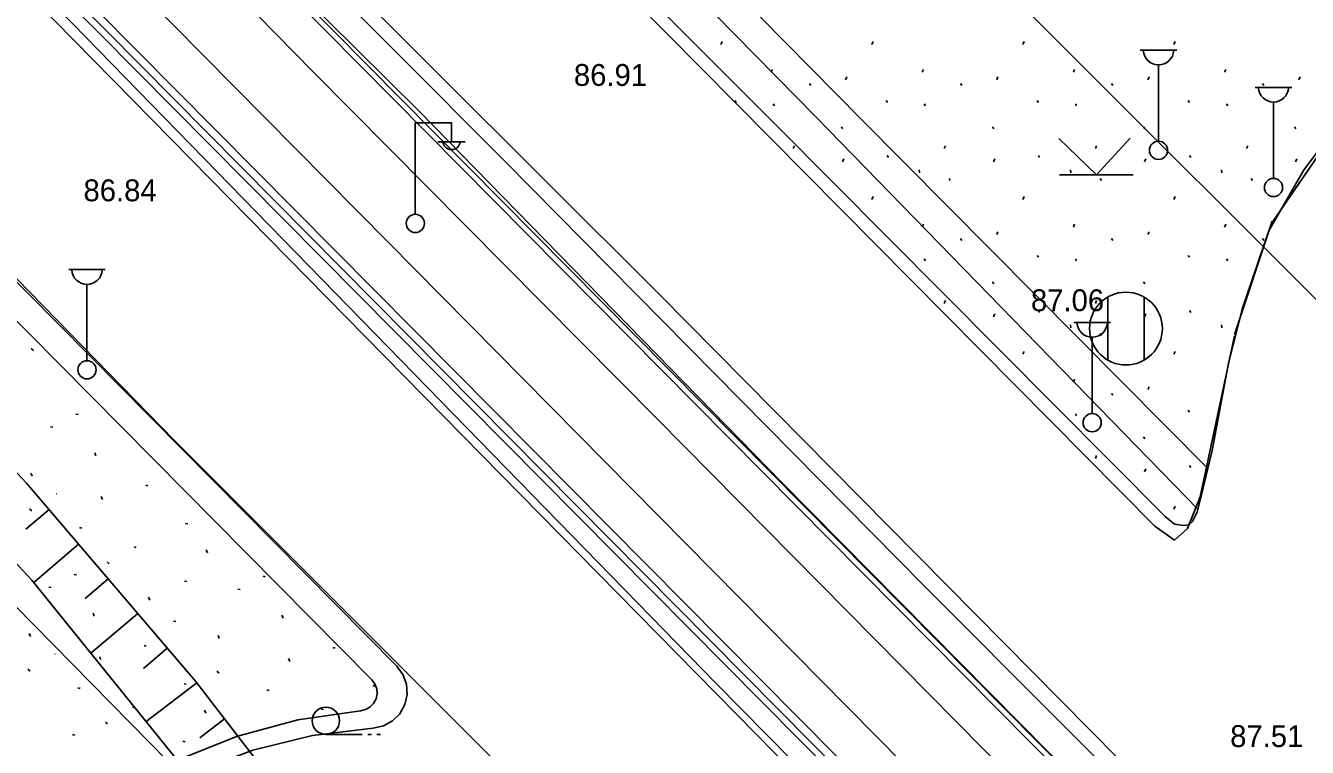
# Model space of a CAD drawing. Extents: x 412225 to 413380, y 4456471 to 4457189.
# Drawn here: x 412532.8 to 412603.2, y 4456807.4 to 4456847.1 of the extents above; entities that cross this region are included whole.
import ezdxf

# ---------------------------------------------------------------- set-up
doc = ezdxf.new("R2010")
doc.units = 0
for name, color, linetype in [('0_HALİHAZIR', 7, 'Continuous'), ('0_KADASTRO', 7, 'Continuous'), ('KALDIRIM', 7, 'Continuous'), ('Level 41', 7, 'Continuous'), ('Level 62', 7, 'Continuous'), ('Level 8', 7, 'Continuous')]:
    doc.layers.add(name, color=color, linetype=linetype)

msp = doc.modelspace()

# ---------------------------------------------------------------- linework, layer by layer
at = {"layer": '0_HALİHAZIR'}
for p, q in [((412594.026, 4456845.719), (412596.026, 4456845.719)), ((412595.026, 4456840.719), (412595.026, 4456844.912)), ((412600.335, 4456843.674), (412602.335, 4456843.674)), ((412601.335, 4456838.674), (412601.335, 4456842.867)), ((412554.212, 4456836.725), (412554.212, 4456841.726)), ((412554.212, 4456841.726), (412556.212, 4456841.726)), ((412556.212, 4456840.726), (412556.212, 4456841.726)), ((412591.613, 4456838.879), (412589.553, 4456840.869)), ((412591.613, 4456838.879), (412593.464, 4456840.889)), ((412555.452, 4456840.686), (412556.952, 4456840.686)), ((412589.593, 4456838.879), (412593.633, 4456838.879)), ((412535.199, 4456833.662), (412537.199, 4456833.662)), ((412536.199, 4456828.662), (412536.199, 4456832.855)), ((412592.236, 4456828.696), (412592.236, 4456832.156)), ((412594.236, 4456828.696), (412594.236, 4456832.156)), ((412590.383, 4456830.757), (412592.383, 4456830.757)), ((412591.383, 4456825.757), (412591.383, 4456829.95)), ((412534.114, 4456820.48), (412532.847, 4456819.399)), ((412535.737, 4456818.578), (412533.274, 4456816.477)), ((412537.36, 4456816.677), (412536.103, 4456815.604)), ((412538.982, 4456814.775), (412536.419, 4456812.587)), ((412540.605, 4456812.873), (412539.298, 4456811.758)), ((412542.224, 4456810.968), (412539.453, 4456808.834)), ((412543.75, 4456808.988), (412542.388, 4456807.938)), ((412549.31, 4456808.134), (412551.31, 4456808.134)), ((412551.61, 4456808.134), (412551.81, 4456808.134)), ((412552.11, 4456808.134), (412552.31, 4456808.134))]:
    msp.add_line(p, q, dxfattribs=at)
for points in [[(412644.931, 4456753.555), (412630.555, 4456767.782), (412604.684, 4456793.709), (412582.154, 4456816.287), (412559.135, 4456839.628), (412534.75, 4456864.124), (412499.888, 4456899.345), (412487.433, 4456911.736), (412459.99, 4456939.333), (412440.337, 4456959.115), (412419.902, 4456979.921), (412392.691, 4457007.039), (412362.588, 4457037.58), (412334.209, 4457066.321), (412297.701, 4457103.437), (412284.18, 4457117.149)], [(412284.17, 4457116.265), (412296.803, 4457102.771), (412316.426, 4457082.291), (412338.061, 4457060.18), (412363.233, 4457034.899), (412383.867, 4457014.022), (412425.083, 4456972.499), (412446.131, 4456951.075), (412463.226, 4456933.647), (412501.75, 4456894.857), (412523.558, 4456872.918), (412554.446, 4456842.344)], [(412283.985, 4457100.322), (412303.353, 4457080.961), (412332.911, 4457051.149), (412362.488, 4457021.336), (412400.253, 4456983.455), (412425.306, 4456957.949), (412451.956, 4456931.175), (412483.613, 4456899.459), (412507.045, 4456875.463), (412533.953, 4456848.693), (412570.746, 4456810.938), (412594.382, 4456786.967), (412618.72, 4456762.275), (412633.267, 4456747.178), (412636.335, 4456744.215)], [(412645.421, 4456754.062), (412629.127, 4456770.178), (412599.147, 4456800.409), (412567.615, 4456832.31), (412536.489, 4456863.396), (412502.72, 4456897.599), (412471.675, 4456928.735), (412445.148, 4456955.565), (412406.259, 4456994.837)], [(412637.165, 4456746.318), (412618.159, 4456765.78), (412589.798, 4456794.375), (412560.702, 4456823.748), (412525.834, 4456858.92), (412495.532, 4456889.87), (412469.975, 4456915.531), (412420.275, 4456965.756), (412393.731, 4456992.619)], [(412414.019, 4456980.608), (412430.818, 4456963.728), (412462.102, 4456931.987), (412481.52, 4456912.466), (412499.923, 4456893.817), (412530.253, 4456863.229), (412548.59, 4456844.546), (412567.492, 4456825.478), (412597.357, 4456795.212), (412619.629, 4456772.724)], [(412412.412, 4456976.824), (412430.58, 4456958.484), (412471.136, 4456917.576), (412494.611, 4456893.791), (412529.094, 4456859.09), (412552.718, 4456835.192), (412591.392, 4456796.015), (412615.481, 4456771.779), (412632.916, 4456754.119)], [(412635.095, 4456744.706), (412621.293, 4456758.968), (412594.514, 4456786.189), (412564.28, 4456816.959), (412527.989, 4456853.886), (412497.963, 4456883.985), (412468.818, 4456913.357), (412423.738, 4456958.933), (412408.728, 4456974.086)], [(412597.174, 4456820.503), (412576.231, 4456842.04), (412561.741, 4456856.791)], [(412565.002, 4456855.835), (412578.684, 4456841.949), (412597.738, 4456822.746)], [(412611.653, 4456848.275), (412608.162, 4456845.364), (412605.073, 4456841.916), (412602.977, 4456839.108), (412601.086, 4456835.793), (412599.636, 4456831.548), (412598.859, 4456828.528), (412597.976, 4456823.732), (412597.387, 4456821.291), (412597.138, 4456820.367), (412596.899, 4456819.837), (412596.688, 4456819.654), (412596.393, 4456819.6), (412595.898, 4456819.675), (412595.383, 4456820.111), (412574.046, 4456841.577), (412560.867, 4456854.796)], [(412554.446, 4456842.344), (412574.337, 4456821.975), (412608.572, 4456787.352), (412635.895, 4456760.057), (412643.635, 4456752.216)], [(412528.743, 4456836.847), (412540.992, 4456824.288), (412559.224, 4456806.047), (412568.503, 4456796.519), (412569.191, 4456795.526), (412569.313, 4456795.068), (412569.042, 4456794.505), (412568.57, 4456794.169), (412567.618, 4456794.057), (412564.023, 4456793.79), (412559.479, 4456793.181), (412554.595, 4456792.173), (412549.493, 4456790.405), (412546.13, 4456788.844), (412542.472, 4456786.095), (412539.525, 4456783.093), (412537.043, 4456779.687), (412534.635, 4456775.789), (412533.752, 4456774.346), (412533.28, 4456774.06), (412532.886, 4456773.972), (412532.31, 4456774.062)], [(412524.256, 4456831.161), (412532.872, 4456821.935), (412542.154, 4456811.059), (412548.102, 4456803.338), (412550.217, 4456799.244), (412550.951, 4456797.332), (412551.196, 4456796.316), (412551.092, 4456795.608), (412550.66, 4456794.812), (412550.141, 4456794.328), (412549.147, 4456793.722), (412547.453, 4456792.678), (412544.824, 4456790.371), (412541.569, 4456787.003), (412538.882, 4456784.219), (412536.669, 4456781.54), (412535.299, 4456779.679), (412534.332, 4456778.383), (412533.704, 4456777.536), (412533.311, 4456777.415), (412532.242, 4456777.481)], [(412532.295, 4456782.824), (412533.199, 4456782.805), (412534.47, 4456783.53), (412535.823, 4456785.423), (412538.722, 4456788.408), (412542.514, 4456792.063), (412545.144, 4456794.354), (412546.599, 4456796.002), (412547.018, 4456797.685), (412546.2, 4456799.629), (412544.925, 4456801.385), (412541.266, 4456806.591), (412533.164, 4456816.614), (412521.975, 4456828.646)]]:
    msp.add_lwpolyline(points, dxfattribs=at)
for centre, radius in [((412595.026, 4456840.219), 0.5), ((412601.335, 4456838.174), 0.5), ((412554.222, 4456836.201), 0.5), ((412593.236, 4456830.426), 2), ((412536.199, 4456828.162), 0.5), ((412591.383, 4456825.257), 0.5), ((412549.31, 4456808.884), 0.75)]:
    msp.add_circle(centre, radius, dxfattribs=at)
for centre, radius, start, end in [((412595.026, 4456845.749), 0.837, 183.298, 356.90719), ((412601.335, 4456843.704), 0.837, 183.298, 356.90719), ((412556.212, 4456840.729), 0.474, 184.83843, 355.14641), ((412536.199, 4456833.692), 0.837, 183.298, 356.90719), ((412591.383, 4456830.787), 0.837, 183.298, 356.90719)]:
    msp.add_arc(centre, radius, start, end, dxfattribs=at)
at = {"layer": '0_KADASTRO'}
msp.add_lwpolyline([(412511.64, 4456802.61), (412523.869, 4456823.705), (412617.056, 4456728.859), (412543.593, 4456703.12), (412527.466, 4456778.138), (412524.42, 4456784.89), (412522.24, 4456788.56), (412519.52, 4456792.85), (412512.99, 4456801.24)], close=True, dxfattribs=at)
at = {"layer": 'KALDIRIM'}
msp.add_line((412528.505, 4456834.72), (412551.839, 4456811.132), dxfattribs=at)
for points in [[(412551.215, 4456809.433), (412551.489, 4456809.497), (412551.735, 4456809.635), (412551.933, 4456809.836), (412552.067, 4456810.084), (412552.126, 4456810.36), (412552.106, 4456810.641), (412552.007, 4456810.906), (412551.839, 4456811.132)], [(412551.215, 4456809.433), (412547.768, 4456808.928), (412544.404, 4456808.02), (412541.171, 4456806.722), (412538.114, 4456805.052), (412535.275, 4456803.034), (412532.693, 4456800.694), (412530.406, 4456798.067), (412528.444, 4456795.188), (412526.835, 4456792.098), (412525.601, 4456788.84), (412524.761, 4456785.459)]]:
    msp.add_lwpolyline(points, dxfattribs=at)
at = {"layer": 'Level 41'}
for p, q in [((412570.993, 4456846.032), (412571.065, 4456846.192)), ((412579.286, 4456846.032), (412579.358, 4456846.192)), ((412587.579, 4456846.032), (412587.651, 4456846.192)), ((412595.872, 4456846.032), (412595.944, 4456846.192)), ((412573.765, 4456844.502), (412573.835, 4456844.662)), ((412577.848, 4456844.094), (412577.919, 4456844.254)), ((412582.058, 4456844.502), (412582.128, 4456844.662)), ((412586.141, 4456844.094), (412586.212, 4456844.254)), ((412590.351, 4456844.502), (412590.421, 4456844.662)), ((412594.434, 4456844.094), (412594.505, 4456844.254)), ((412598.644, 4456844.502), (412598.714, 4456844.662)), ((412602.727, 4456844.094), (412602.798, 4456844.254)), ((412575.86, 4456843.886), (412575.931, 4456843.78)), ((412584.153, 4456843.886), (412584.224, 4456843.78)), ((412592.446, 4456843.886), (412592.517, 4456843.78)), ((412600.739, 4456843.886), (412600.81, 4456843.78)), ((412571.775, 4456842.957), (412571.846, 4456842.85)), ((412580.068, 4456842.957), (412580.139, 4456842.85)), ((412588.361, 4456842.957), (412588.432, 4456842.85)), ((412596.654, 4456842.957), (412596.725, 4456842.85)), ((412573.874, 4456842.765), (412573.945, 4456842.658)), ((412582.167, 4456842.765), (412582.238, 4456842.658)), ((412590.46, 4456842.765), (412590.531, 4456842.658)), ((412598.753, 4456842.765), (412598.824, 4456842.658)), ((412577.612, 4456841.504), (412577.683, 4456841.397)), ((412585.905, 4456841.504), (412585.976, 4456841.397)), ((412594.198, 4456841.504), (412594.269, 4456841.397)), ((412602.491, 4456841.504), (412602.562, 4456841.397)), ((412574.971, 4456840.311), (412575.042, 4456840.47)), ((412583.264, 4456840.311), (412583.335, 4456840.47)), ((412591.557, 4456840.311), (412591.628, 4456840.47)), ((412599.85, 4456840.311), (412599.921, 4456840.47)), ((412577.67, 4456839.582), (412577.742, 4456839.742)), ((412580.135, 4456839.927), (412580.206, 4456839.82)), ((412585.963, 4456839.582), (412586.035, 4456839.742)), ((412588.428, 4456839.927), (412588.499, 4456839.82)), ((412594.256, 4456839.582), (412594.328, 4456839.742)), ((412596.721, 4456839.927), (412596.792, 4456839.82)), ((412602.549, 4456839.582), (412602.621, 4456839.742)), ((412581.893, 4456839.136), (412581.911, 4456838.976)), ((412583.523, 4456838.666), (412583.593, 4456838.559)), ((412590.186, 4456839.136), (412590.204, 4456838.976)), ((412591.816, 4456838.666), (412591.886, 4456838.559)), ((412598.479, 4456839.136), (412598.497, 4456838.976)), ((412600.109, 4456838.666), (412600.179, 4456838.559)), ((412579.286, 4456837.522), (412579.358, 4456837.682)), ((412587.579, 4456837.522), (412587.651, 4456837.682)), ((412595.872, 4456837.522), (412595.944, 4456837.682)), ((412582.058, 4456835.992), (412582.128, 4456836.152)), ((412590.351, 4456835.992), (412590.421, 4456836.152)), ((412598.644, 4456835.992), (412598.714, 4456836.152)), ((412584.153, 4456835.376), (412584.224, 4456835.27)), ((412586.141, 4456835.584), (412586.212, 4456835.744)), ((412592.446, 4456835.376), (412592.517, 4456835.27)), ((412594.434, 4456835.584), (412594.505, 4456835.744)), ((412600.739, 4456835.376), (412600.81, 4456835.27)), ((412588.361, 4456834.447), (412588.432, 4456834.34)), ((412596.654, 4456834.447), (412596.725, 4456834.34)), ((412582.167, 4456834.255), (412582.238, 4456834.148)), ((412590.46, 4456834.255), (412590.531, 4456834.148)), ((412598.753, 4456834.255), (412598.824, 4456834.148)), ((412585.905, 4456832.994), (412585.976, 4456832.887)), ((412594.198, 4456832.994), (412594.269, 4456832.887)), ((412583.264, 4456831.801), (412583.335, 4456831.96)), ((412591.557, 4456831.801), (412591.628, 4456831.96)), ((412585.963, 4456831.072), (412586.035, 4456831.232)), ((412588.428, 4456831.417), (412588.499, 4456831.31)), ((412594.256, 4456831.072), (412594.328, 4456831.232)), ((412596.721, 4456831.417), (412596.792, 4456831.31)), ((412590.186, 4456830.626), (412590.204, 4456830.466)), ((412598.479, 4456830.626), (412598.497, 4456830.466)), ((412591.816, 4456830.156), (412591.886, 4456830.049)), ((412533.138, 4456829.322), (412533.265, 4456829.222)), ((412533.138, 4456829.322), (412533.265, 4456829.222)), ((412587.579, 4456829.012), (412587.651, 4456829.172)), ((412595.872, 4456829.012), (412595.944, 4456829.172)), ((412590.351, 4456827.482), (412590.421, 4456827.642)), ((412598.644, 4456827.482), (412598.663, 4456827.527)), ((412592.446, 4456826.866), (412592.517, 4456826.76)), ((412594.434, 4456827.074), (412594.505, 4456827.234)), ((412596.654, 4456825.937), (412596.725, 4456825.83)), ((412535.586, 4456825.73), (412535.712, 4456825.706)), ((412535.586, 4456825.73), (412535.712, 4456825.706)), ((412590.46, 4456825.745), (412590.531, 4456825.638)), ((412534.203, 4456825.031), (412534.329, 4456825.005)), ((412534.203, 4456825.031), (412534.329, 4456825.005)), ((412594.198, 4456824.484), (412594.269, 4456824.377)), ((412536.691, 4456823.431), (412536.628, 4456823.595)), ((412536.691, 4456823.431), (412536.628, 4456823.595)), ((412591.557, 4456823.291), (412591.628, 4456823.45)), ((412533.184, 4456822.318), (412533.122, 4456822.48)), ((412533.184, 4456822.318), (412533.122, 4456822.48)), ((412594.256, 4456822.562), (412594.328, 4456822.722)), ((412596.721, 4456822.907), (412596.792, 4456822.8)), ((412539.421, 4456821.815), (412539.547, 4456821.79)), ((412539.421, 4456821.815), (412539.547, 4456821.79)), ((412534.532, 4456821.34), (412534.54, 4456821.339)), ((412534.532, 4456821.34), (412534.54, 4456821.339)), ((412537.049, 4456821.045), (412536.985, 4456821.208)), ((412537.049, 4456821.045), (412536.985, 4456821.208)), ((412533.048, 4456820.517), (412533.174, 4456820.417)), ((412533.048, 4456820.517), (412533.174, 4456820.417)), ((412595.872, 4456820.502), (412595.944, 4456820.662)), ((412541.615, 4456819.724), (412541.741, 4456819.699)), ((412541.615, 4456819.724), (412541.741, 4456819.699)), ((412535.792, 4456819.49), (412535.918, 4456819.465)), ((412535.792, 4456819.49), (412535.918, 4456819.465)), ((412538.781, 4456818.435), (412538.906, 4456818.409)), ((412538.781, 4456818.435), (412538.906, 4456818.409)), ((412542.812, 4456818.114), (412542.749, 4456818.277)), ((412542.812, 4456818.114), (412542.749, 4456818.277)), ((412537.298, 4456817.612), (412537.424, 4456817.511)), ((412537.298, 4456817.612), (412537.424, 4456817.511)), ((412535.496, 4456816.925), (412535.622, 4456816.9)), ((412535.496, 4456816.925), (412535.622, 4456816.9)), ((412545.863, 4456816.819), (412545.989, 4456816.794)), ((412545.863, 4456816.819), (412545.989, 4456816.794)), ((412534.113, 4456816.225), (412534.239, 4456816.199)), ((412534.113, 4456816.225), (412534.239, 4456816.199)), ((412541.556, 4456816.559), (412541.682, 4456816.534)), ((412541.556, 4456816.559), (412541.682, 4456816.534)), ((412544.48, 4456816.119), (412544.606, 4456816.093)), ((412544.48, 4456816.119), (412544.606, 4456816.093)), ((412539.642, 4456815.509), (412539.577, 4456815.672)), ((412539.642, 4456815.509), (412539.577, 4456815.672)), ((412536.601, 4456814.626), (412536.538, 4456814.79)), ((412536.601, 4456814.626), (412536.538, 4456814.79)), ((412546.969, 4456814.52), (412546.905, 4456814.684)), ((412546.969, 4456814.52), (412546.905, 4456814.684)), ((412540.949, 4456814.361), (412541.075, 4456814.336)), ((412540.949, 4456814.361), (412541.075, 4456814.336)), ((412533.094, 4456813.512), (412533.032, 4456813.674)), ((412533.094, 4456813.512), (412533.032, 4456813.674)), ((412543.461, 4456813.406), (412543.399, 4456813.568)), ((412543.461, 4456813.406), (412543.399, 4456813.568)), ((412539.331, 4456813.01), (412539.457, 4456812.984)), ((412539.331, 4456813.01), (412539.457, 4456812.984)), ((412549.699, 4456812.904), (412549.825, 4456812.878)), ((412549.699, 4456812.904), (412549.825, 4456812.878)), ((412534.442, 4456812.535), (412534.45, 4456812.533)), ((412534.442, 4456812.535), (412534.45, 4456812.533)), ((412536.958, 4456812.239), (412536.895, 4456812.402)), ((412536.958, 4456812.239), (412536.895, 4456812.402)), ((412544.809, 4456812.429), (412544.818, 4456812.427)), ((412544.809, 4456812.429), (412544.818, 4456812.427)), ((412547.326, 4456812.133), (412547.263, 4456812.296)), ((412547.326, 4456812.133), (412547.263, 4456812.296)), ((412532.958, 4456811.711), (412533.084, 4456811.611)), ((412532.958, 4456811.711), (412533.084, 4456811.611)), ((412543.326, 4456811.605), (412543.452, 4456811.505)), ((412543.326, 4456811.605), (412543.452, 4456811.505)), ((412535.702, 4456810.684), (412535.828, 4456810.659)), ((412535.702, 4456810.684), (412535.828, 4456810.659)), ((412541.525, 4456810.919), (412541.651, 4456810.893)), ((412541.525, 4456810.919), (412541.651, 4456810.893)), ((412546.07, 4456810.578), (412546.196, 4456810.553)), ((412546.07, 4456810.578), (412546.196, 4456810.553)), ((412551.892, 4456810.813), (412552.018, 4456810.787)), ((412551.892, 4456810.813), (412552.018, 4456810.787)), ((412538.691, 4456809.629), (412538.816, 4456809.603)), ((412538.691, 4456809.629), (412538.816, 4456809.603)), ((412542.722, 4456809.309), (412542.658, 4456809.471)), ((412542.722, 4456809.309), (412542.658, 4456809.471)), ((412549.059, 4456809.523), (412549.184, 4456809.497)), ((412549.059, 4456809.523), (412549.184, 4456809.497)), ((412537.208, 4456808.807), (412537.334, 4456808.706)), ((412537.208, 4456808.807), (412537.334, 4456808.706)), ((412535.406, 4456808.119), (412535.532, 4456808.095)), ((412535.406, 4456808.119), (412535.532, 4456808.095)), ((412541.466, 4456807.753), (412541.592, 4456807.729)), ((412541.466, 4456807.753), (412541.592, 4456807.729))]:
    msp.add_line(p, q, dxfattribs=at)
at = {"layer": 'Level 62'}
for p, q in [((412497.295, 4456899.362), (412643.049, 4456752.063)), ((412643.265, 4456752.271), (412497.51, 4456899.572)), ((412490.887, 4456893.113), (412636.434, 4456746.08)), ((412491.172, 4456893.395), (412636.692, 4456746.295)), ((412565.004, 4456849.724), (412594.825, 4456819.58)), ((412605.356, 4456842.229), (412601.264, 4456836.251)), ((412529.02, 4456836.332), (412553.204, 4456811.885)), ((412601.264, 4456836.328), (412599.197, 4456830.103)), ((412599.197, 4456830.026), (412597.307, 4456821.177)), ((412597.307, 4456821.177), (412596.613, 4456819.442))]:
    msp.add_line(p, q, dxfattribs=at)
for points in [[(412414.019, 4456980.608), (412430.818, 4456963.728), (412462.102, 4456931.987), (412481.52, 4456912.466), (412499.923, 4456893.817), (412530.253, 4456863.229), (412548.59, 4456844.546), (412567.492, 4456825.478), (412597.357, 4456795.212), (412619.629, 4456772.724)], [(412412.412, 4456976.824), (412430.58, 4456958.484), (412471.136, 4456917.576), (412494.611, 4456893.791), (412529.094, 4456859.09), (412552.718, 4456835.192), (412591.392, 4456796.015), (412615.481, 4456771.779), (412632.916, 4456754.119)], [(412594.825, 4456819.58), (412595.909, 4456818.811), (412596.613, 4456819.442)], [(412551.912, 4456808.483), (412552.47, 4456808.6), (412552.971, 4456808.87), (412553.376, 4456809.27), (412553.652, 4456809.769), (412553.777, 4456810.324), (412553.739, 4456810.893), (412553.543, 4456811.427), (412553.204, 4456811.885)], [(412551.912, 4456808.483), (412548.572, 4456808.067), (412545.304, 4456807.26), (412542.155, 4456806.073), (412539.167, 4456804.524), (412536.382, 4456802.632), (412533.84, 4456800.426), (412531.576, 4456797.936), (412529.621, 4456795.195), (412528.003, 4456792.244), (412526.744, 4456789.122), (412525.862, 4456785.874), (412525.369, 4456782.544), (412525.272, 4456779.18), (412525.573, 4456775.827), (412526.266, 4456772.534)]]:
    msp.add_lwpolyline(points, dxfattribs=at)
at = {"layer": 'Level 8'}
msp.add_lwpolyline([(412706.1, 4457175.965), (412751.217, 4457041.463), (412764.575, 4457001.385), (412790.361, 4457003.87), (412821.118, 4456953.851), (412699.954, 4456860.338), (412631.485, 4456804.219), (412585.777, 4456849.927), (412523.439, 4456912.266), (412460.309, 4456974.831), (412403.512, 4457031.625), (412342.192, 4457092.946), (412287.774, 4457146.913), (412253.259, 4457181.199)], dxfattribs=at)

# ---------------------------------------------------------------- texts
at = {"layer": '0_HALİHAZIR'}
for s, p in [('86.91', (412562.93, 4456843.755)), ('86.84', (412536.008, 4456837.419)), ('87.06', (412588.021, 4456831.38)), ('87.51', (412598.959, 4456807.439))]:
    msp.add_text(s, height=1.2, dxfattribs=at).set_placement(p)

doc.saveas('drawing.dxf')
